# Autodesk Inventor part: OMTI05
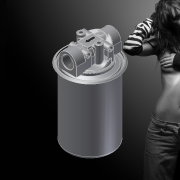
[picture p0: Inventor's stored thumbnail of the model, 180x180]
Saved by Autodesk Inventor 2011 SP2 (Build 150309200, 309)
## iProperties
Created: 2016-02
Part Number: OMTI05
Document SubType Name: Modeling
Designer: Столбов
Density: 1 g/cm^3
Author: Столбов
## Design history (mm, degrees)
derived "513_OMTI05.iam"
sketch "Эскиз2"
  geometry: L1 (0, -30.5)-(0, 0) reference; L2 (10, -25.25)-(5, -18.25); L3 (5, -18.25)-(7.5, -18.25); L4 (7.5, -18.25)-(7.5, -5.25); L5 (7.5, -5.25)-(12.5, -5.25); L6 (12.5, -5.25)-(12.5, -18.25); L7 (12.5, -18.25)-(15, -18.25); L8 (15, -18.25)-(10, -25.25); C1 r 11.5 at (10.25, -15.25) reference; 1 further point
  constraints: 14 end point, 3 perpendicular, 1 parallel
  dimensions: "d1" = 5 distance between parallel lines of L6 L4; "d2" = 2.5 distance from line of L2.start L4 (= 0.5 x d1); "d3" = 10 distance of L7.end L2.end; "d4" = 5 horizontal distance of L2.start L2.end (= 0.5 x d3); "d5" = 7 distance from line of L3 L2.start; "d6" = 0 distance between parallel lines of L3 L7; "d7" = 20 distance from line of L5 L2.start; "d9" = 10 distance from line of L5 C1.centre; "d10" = 7.5 distance between parallel lines of L4 L1
extrude "Выдавливание1" join sketch "Эскиз2" distance "d11" = 1; taper "d12" = 0 deg
sketch "Эскиз3" dims "d0" = 10, "d1" = 5, "d34" = 10, "d35" = 10, "d45" = 8.566, "d55" = 8
  geometry: L1 (-65.107, 4)-(-65.107, 23) reference; L2 (2.393, 6.5)-(2.393, 31) reference; C1 r 2.5 at (-39.107, 31); C2 r 2.5 at (-3.607, 31); 4 further points
  constraints: 2 centre point, 2 coincident
  dimensions: "d17" = 26 distance from line of point (-39.107, 31) L1; "d18" = 0 vertical distance of point (-39.107, 31) point (-45.107, 31); "d19" = 5 diameter of C1; "d20" = 0 vertical distance of point (-39.107, 31) point (-3.607, 31); "d21" = 6 distance from line of L2 point (-3.607, 31); "d22" = 5 diameter of C2
extrude "Выдавливание2" cut sketch "Эскиз3" stored distance "d23" = 80; taper "d24" = 0 deg
hole "Отверстие1" diameter "d27" = 8.566; diameter "d45" = 8.566; stored, may be unused: countersink angle "d31" = 90 deg, drill point angle "d33" = 118 deg; dims "d0" = 10, "d1" = 5, "d25" = 10, "d26" = 10, "d28" = 8, "d29" = 9.8, "d30" = 2, "d32" = 10, "d34" = 10, "d35" = 10, "d55" = 8
hole "Отверстие2" diameter "d36" = 8.566; stored, may be unused: countersink angle "d40" = 90 deg, drill point angle "d42" = 118 deg; dims "d34" = 10, "d35" = 10, "d37" = 8, "d38" = 9.8, "d39" = 2, "d41" = 10
hole "Отверстие3" diameter "d45" = 8.566; stored, may be unused: countersink angle "d49" = 90 deg, drill point angle "d51" = 118 deg; dims "d0" = 10, "d1" = 5, "d34" = 10, "d35" = 10, "d43" = 10, "d44" = 10, "d46" = 8, "d47" = 9.8, "d48" = 2, "d50" = 10, "d55" = 8
hole "Отверстие4" diameter "d54" = 8.566; stored, may be unused: countersink angle "d58" = 90 deg, drill point angle "d60" = 118 deg; dims "d52" = 10, "d53" = 10, "d55" = 8, "d56" = 9.8, "d57" = 2, "d59" = 10
sketch "Эскиз4"
  geometry: 3 further points
  constraints: 2 horizontal alignment
extrude "Выдавливание3" join sketch "Эскиз4" distance "d61" = 22; taper "d62" = 0 deg
sketch "Эскиз5"
  geometry: L1 (36, 0)-(36, 19) reference; 3 further points
  dimensions: "d63" = 18 distance from line of L1 point (18, 19) (= 0.5 x d64); "d64" = 36 distance of L1.end point (0, 19) (derived); "d65" = 0 vertical distance of L1.end point (18, 19)
hole "Отверстие5" sketch "Эскиз5" at (18, 19) diameter "d66" = 24.117; stored, may be unused: countersink angle "d70" = 90 deg, drill point angle "d72" = 118 deg; dims "d67" = 16, "d68" = 26.5, "d69" = 2, "d71" = 22
sketch "Эскиз6"
  geometry: 3 further points
  constraints: 2 horizontal alignment
extrude "Выдавливание4" join sketch "Эскиз6" distance "d73" = 17; taper "d74" = 0 deg
sketch "Эскиз7"
  geometry: 4 further points
  dimensions: "d75" = 36 distance of point (0, -19.5) point (36, -19.5) (derived); "d76" = 18 distance of point (0, -19.5) point (18, -19.5) (= 0.5 x d75); "d77" = 0 vertical distance of point (36, -19.5) point (18, -19.5)
hole "Отверстие6" sketch "Эскиз7" at (18, -19.5) diameter "d78" = 24.117; stored, may be unused: countersink angle "d82" = 90 deg, drill point angle "d84" = 118 deg; dims "d79" = 16, "d80" = 26.5, "d81" = 2, "d83" = 17
node "Твердое тело1"
node "T05.ipt:1"
sketch "CS06-01-CL.ipt:1"
sketch "CS05-02B.ipt:1"
